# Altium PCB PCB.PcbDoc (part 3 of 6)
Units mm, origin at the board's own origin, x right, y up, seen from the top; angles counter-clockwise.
Board outline 101.6 x 101.61 mm, 4 copper layers (Top Layer, GND, POWER, Bottom Layer), stack 1.371 mm thick; 506 components, 346 nets, 1798 pads, 1471 vias.
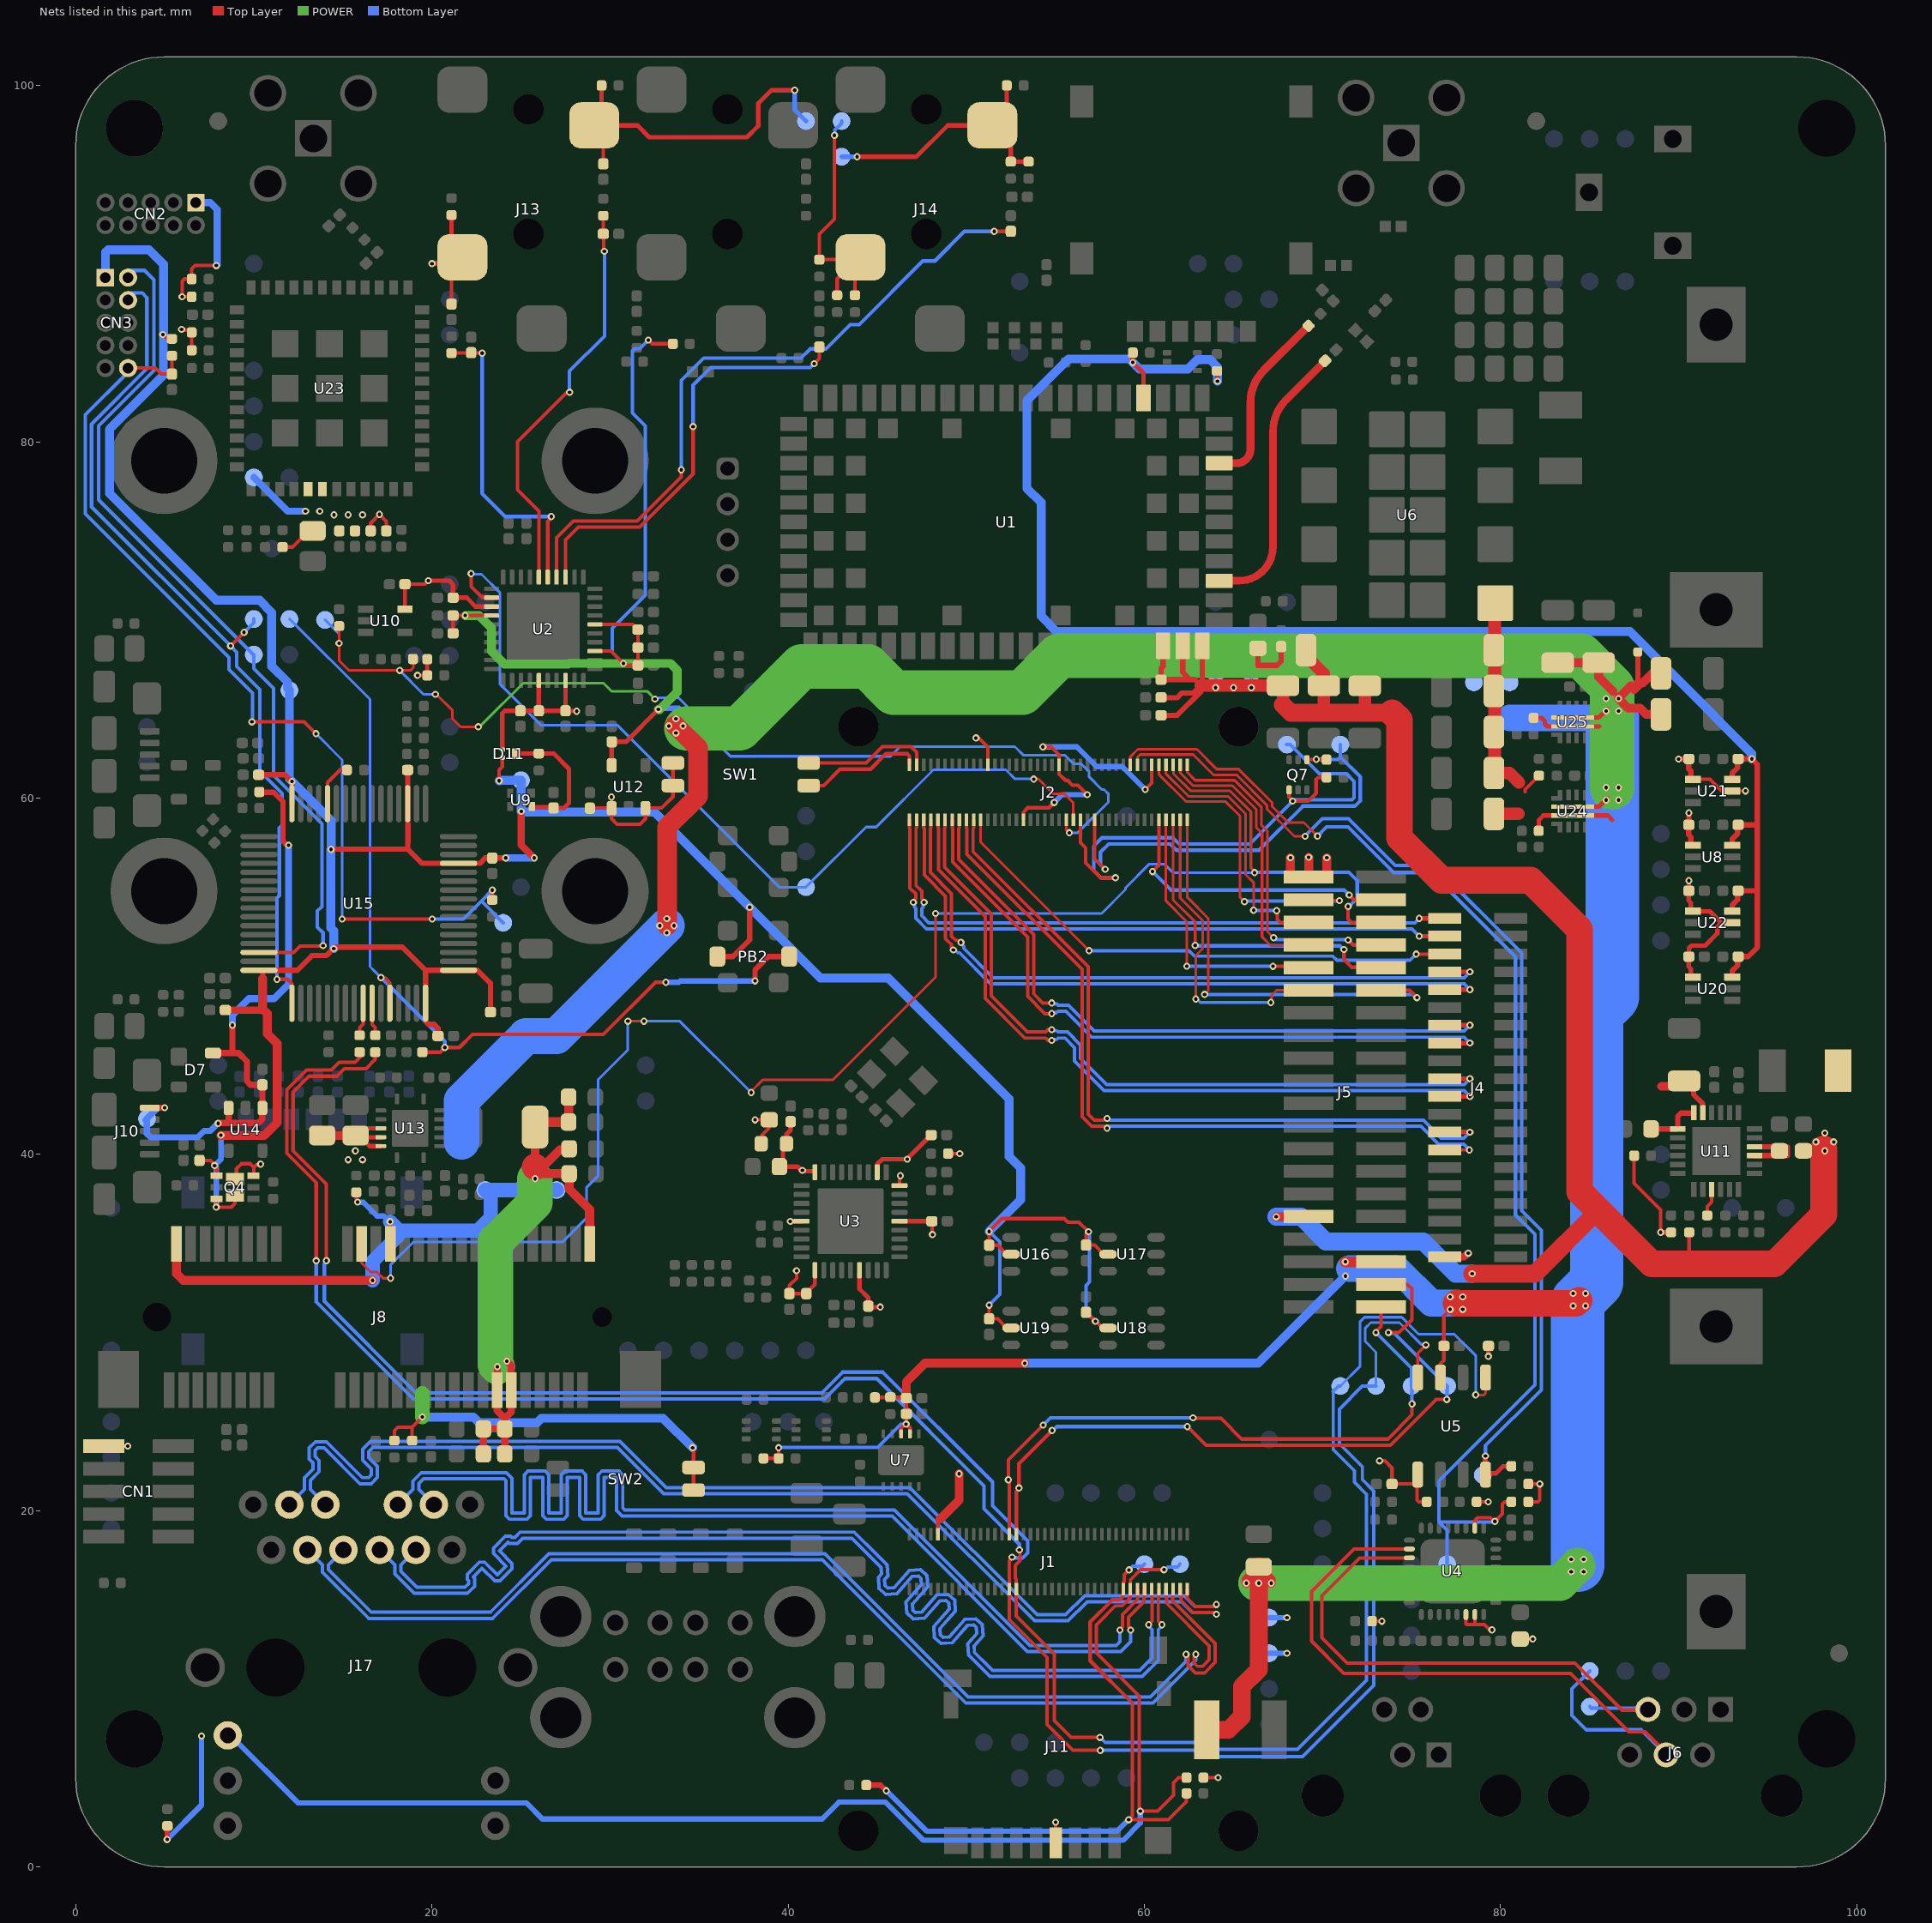
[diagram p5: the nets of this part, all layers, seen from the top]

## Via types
v1: diameter 0.4, hole 0.2, Top Layer to Bottom Layer, tented both sides, 1471 vias

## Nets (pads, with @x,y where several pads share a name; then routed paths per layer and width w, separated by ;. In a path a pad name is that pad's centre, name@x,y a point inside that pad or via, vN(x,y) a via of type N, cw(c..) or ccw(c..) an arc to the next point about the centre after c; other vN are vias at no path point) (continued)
+1V8: 1V8.X C24.2 C25.2 C26.2 C27.2 C28.2 C87.2 R22.2 U2.13 U2.16 U2.34 U12.5 | length 56
  Top Layer w0.2: C25.2@21.185,69.25 C28.2@21.185,70.25 U2.34@23.35,70.25 ; U2.13@29.15,68.25 30.06,68.25 v1(30.75,67.56) 30.86,67.45 C24.2@31.565,67.45 C27.2@31.565,68.45 C26.2@31.565,69.45 31.265,69.75 U2.16@29.15,69.75 ; v1(32.143,85.706) 32.154,85.706 32.36,85.5 R22.2@33.525,85.5
  Top Layer w0.25: U12.5@30.089,61.837 30.089,63.149 C87.2@30.1,63.16 30.893,63.16 v1(32.709,64.976)
  POWER w0.5: v1(21.872,70.246) 22.654,70.246 23.35,69.55 23.35,68.251 24.076,67.525 27.641,67.525 27.677,67.56 v1(30.75,67.56) 33.385,67.56 33.77,67.175 33.77,65.966 32.78,64.976 v1(32.709,64.976)
  Bottom Layer w0.2: v1(30.75,67.56) 30.126,68.184 30.126,69.526 31.985,71.385 31.985,80.89 31.25,81.625 31.25,85.103 31.367,85.22 31.657,85.22 v1(32.143,85.706)
  Bottom Layer w0.3: v1(32.709,64.976) 32.736,64.976 32.8,65.04 33.866,65.04 34.906,64 1V8.X@35,64
+1V8_M: C30.2 C135.2 C137.2 C139.2 R1.2 R2.2 U1.4 U8.6 U20.6 U21.6 U22.6 | length 92.2
  Top Layer w0.25: v1(59.349,84.448) 59.95,83.847 U1.4@59.95,82.45 ; R1.2@64.075,83.975 64.088,83.963 64.088,83.412 v1(64.1,83.4)
  Top Layer w0.3: v1(59.349,84.448) R2.2@59.35,85 ; U20.6@93,49.95 93,50.3 93.3,50.6 C135.2@93.3,51.065 ; U22.6@93,53.65 93,54 93.3,54.3 C139.2@93.3,54.765 ; U8.6@93,57.35 93,57.7 93.3,58 C30.2@93.3,58.465 ; U21.6@93,61.05 93,61.4 93.3,61.7 C137.2@93.3,62.165 ; C135.2@93.335,51.1 93.894,51.1 94.413,51.619 94.413,58.5 ; C139.2@93.335,54.8 94.413,54.8 ; C30.2@93.335,58.5 94.413,58.5 ; C137.2@93.335,62.2 v1(94.1,62.2) 94.413,61.887 94.413,58.5
  Bottom Layer w0.5: v1(64.1,83.4) 64.1,84.189 63.684,84.606 62.962,84.606 62.439,84.082 59.715,84.082 59.147,84.65 55.749,84.65 53.4,82.301 53.4,77.4 54.2,76.6 54.2,70.212 55.062,69.35 87.25,69.35 89.95,66.65 94.1,62.5 v1(94.1,62.2)
+3V3: 3V3_1.X 3V3_2.X C11.2 C12.2 C13.2 C14.2 C15.2 C18.2 C29.2 C32.1 C35.2 C36.2 C37.2 C43.2 C57.2 C59.2 C70.2 C71.2 C76.2 C88.1 C134.2 C136.2 C138.2 CN1.1 CN2.1 D11.2 J1.72 J2.23 J2.34 J2.43 J2.69 J4.20 J5.1 J11.4 L4.1 LoRa_3V3.X Q4.D Q4.D2 R9.2 R10.2 R11.2 R13.2 R14.2 R34.1 R35.1 R43.2 R45.2 R46.2 R47.2 R48.2 R54.2 R71.2 R76.1 R93.2 R94.2 R95.2 R116.2 SW1.3 SW1.4 SW2.3 SW2.4 U2.5 U2.8 U2.33 U3.15 U3.23 U3.27 U4.30 U4.31 U5.5 U8.1 U10.5 U12.1 U12.3 U20.1 U21.1 U21.5 U22.1 U22.5 U23.5 U23.6 | length 155.2
  Top Layer w0.15: U21.5@93,60.4 v1(93.75,60.4)
  Top Layer w0.2: CN1.1@1.578,23.625 v1(2.926,23.625) ; v1(5.941,86.308) 5.979,86.27 6.382,86.27 R10.2@6.514,86.138 R11.2@6.514,85.138 ; R14.2@6.509,88.138 v1(5.974,88.138) 5.974,89.011 6.101,89.138 R9.2@6.509,89.138 6.509,89.694 6.705,89.89 v1(7.891,89.89) ; Q4.D2@8.945,38.622 9.025,38.702 9.025,39.196 9.304,39.475 9.8,39.475 10,39.275 ; Q4.D@9.985,38.805 10,38.82 10,39.275 ; v1(10.38,39.455) 10.342,39.417 10.142,39.417 10,39.275 ; R13.2@11.615,74.09 12.173,74.09 13.083,75 C12.2@13.3,75 ; C15.2@16.56,75 16.56,75.435 v1(17.05,75.925) 17.44,75.535 C11.2@17.44,75 ; R93.2@17.891,23.94 17.891,24.489 18.091,24.689 18.891,24.689 ; U10.5@18.485,70.605 C32.1@18.485,72.005 19.605,72.005 v1(19.8,72.2) ; R94.2@18.891,23.94 18.891,24.689 ; v1(19.191,66.89) R34.1@19.741,66.89 R35.1@19.741,67.79 ; v1(19.462,25.259) v1(19.462,25.259) 18.891,24.689 ; C88.1@28.874,59.433 C88.1@28.87,59.433 28.874,59.438 U12.1@30.089,59.438 ; v1(30.08,60.056) 30.085,60.052 30.085,59.442 U12.1@30.089,59.438 ; SW1.3@33.529,61.973 SW1.4@33.529,60.703 33.529,60.067 32.9,59.438 U12.3@31.989,59.438 31.989,58.838 31.689,58.538 30.389,58.538 30.089,58.838 U12.1@30.089,59.438 ; v1(34.639,23.538) 34.639,23.483 34.685,23.438 SW2.4@34.685,22.425 SW2.3@34.685,21.155 ; v1(38.143,41.938) C76.2@38.939,41.938 38.914,41.913 38.914,41.461 38.53,41.076 38.53,40.65 L4.1@38.48,40.6 ; U3.27@46.25,38.25 46.25,38.75 v1(46.3,38.8) ; C70.2@48.065,36.25 48.082,36.233 48.082,35.518 v1(48.1,35.5) ; 48.407,19.406 48.407,18.996 48.41,18.994 J1.72@48.41,18.685 ; R54.2@48.976,40.047 v1@49.638,40.047 ; v1(50.545,63.377) 50.578,63.344 50.736,63.344 51.21,62.871 J2.23@51.21,61.865 ; J2.34@53.21,58.785 53.21,59.21 53.457,59.457 54.64,59.457 v1(54.935,59.752) ; v1(54.301,62.879) 54.753,62.879 55.21,62.421 J2.43@55.21,61.865 55.21,61.35 55.56,61 55.679,61 55.962,60.717 56.264,60.717 v1(56.791,60.19) ; J11.4@55.018,1.362 v1(55.018,2.518) ; v1(60.044,60.482) 60.41,60.849 J2.69@60.41,61.865 ; R116.2@63.314,5.018 v1(64.139,5.018) ; R43.2@72.78,13.8 v1(73.33,13.8) ; v1(73.2,22.8) 73.5,22.8 73.9,22.4 C59.2@73.9,21.5 75.17,21.5 75.238,21.5 U5.5@75.3,21.562 ; R48.2@75.85,20.5 75.4,20.5 75.3,20.6 U5.5@75.3,21.562 ; U4.30@78.05,14.175 78.05,13.65 78.094,13.606 78.594,13.606 ; U4.31@78.55,14.175 78.55,13.65 78.594,13.606 ; R46.2@78.65,20.5 v1(79.3,20.5) ; C18.2@79.3,29.265 C18.2@79.315,29.25 ; v1(79.515,13.309) 79.509,13.309 79.5,13.3 79.4,13.3 79.094,13.606 78.594,13.606 ; C57.2@81.1,12.8 v1(81.8,12.8) ; R47.2@81.55,20.5 82.1,20.5 82.2,20.6 v1(82.2,21.5) R45.2@81.55,21.5 ; R71.2@87.495,39.93 87.495,38.38 88.986,36.889 v1(88.986,35.625) ; U21.1@90.8,61.05 91.75,61.05 92.4,60.4 U21.5@93,60.4 ; U5.5@75.3,21.562 75.345,21.607 U5.5@75.345,22.025 75.3,21.98 75.3,21.63 U5.5@75.3,21.562
  Top Layer w0.25: v1(19.8,72.2) 20.97,72.2 21.185,71.985 C43.2@21.185,71.25 21.95,71.25 22.45,70.75 U2.33@23.35,70.75 ; D11.2@23.95,62.725 23.95,64.754 24.096,64.9 C35.2@24.967,64.9 C36.2@26,64.9 ; U2.5@26,66.6 C36.2@26,64.9 ; 27.5,65.694 C37.2@27.5,64.9 ; 27.5,65.694 27.5,66.3 U2.8@27.5,66.6 ; v1(28.125,64.875) 28.113,64.888 27.513,64.888 C37.2@27.5,64.9 ; U3.15@44,33.3 44,32.452 44.5,31.952 C71.2@44.5,31.485 44.553,31.432 v1(45.168,31.432) ; U3.23@46.25,36.25 C70.2@48.065,36.25 ; U5.5@75.17,21.5 75.3,21.63 75.345,21.675 U5.5@75.345,22.025 ; v1(79.309,28.666) 79.312,28.669 79.312,29.247 C18.2@79.315,29.25 ; v1(88.986,35.625) R76.1@89.568,35.625 ; C138.2@90.536,54.771 C138.2@90.559,54.794 ; v1(90.565,55.365) C138.2@90.565,54.8 C138.2@90.559,54.794 ; U20.1@90.8,49.95 90.726,49.95 90.676,50 90.676,50.424 90.559,50.541 90.559,51.094 C134.2@90.565,51.1 90.565,51.578 90.711,51.725 91.484,51.725 92.165,52.406 92.165,52.765 92.4,53 ; U22.5@93,53 92.4,53 ; C36.2@26,64.9 C37.2@27.5,64.9 ; C138.2@90.559,54.794 90.559,54.241 90.676,54.124 90.676,53.7 90.726,53.65 U22.1@90.8,53.65 91.75,53.65 92.4,53
  Top Layer w0.3: v1(5.132,1.547) 5.14,1.556 5.14,2.181 5.149,2.19 R95.2@5.149,2.306 ; v1(89.994,62.194) C136.2@90.559,62.194 ; v1(90.565,59.165) C29.2@90.565,58.5 90.559,58.494 90.559,57.941 90.676,57.824 90.676,57.4 90.726,57.35 U8.1@90.8,57.35 ; C136.2@90.565,62.2 C136.2@90.559,62.194 ; U21.1@90.8,61.05 90.726,61.05 90.676,61.1 90.676,61.524 90.559,61.641 C136.2@90.559,62.194
  Top Layer w0.4: J4.20@76.85,34.25 77.958,34.25 78.159,34.451 v1(78.181,34.451)
  Top Layer w0.5: 48.533,19.531 49.6,20.598 v1(49.6,22.075) ; J5.1@68.2,55.547 v1(68.2,56.65) ; J5.1@69.218,55.565 69.225,55.572 v1(69.225,56.675) ; J5.1@70.243,55.547 v1(70.243,56.65)
  POWER w0.8: v1(19.462,25.259) 19.462,26.597
  Bottom Layer w0.3: v1(5.132,1.547) 7.062,3.478 v1(7.062,7.357) ; v1(50.545,63.377) v1@50.572,63.377 ; v1(54.301,62.879) 56.202,62.879 57.316,61.765 58.761,61.765 v1(60.044,60.482) ; v1(54.935,59.752) 55.373,60.19 v1(56.791,60.19) ; 3V3_1.X@67,12 v1(68,12) ; 3V3_2.X@67,14 v1(68,14)
  Bottom Layer w0.4: CN2.1@6.749,93.428 7.553,93.428 7.935,93.046 7.935,89.934 v1(7.891,89.89) ; LoRa_3V3.X@10,78 11.9,76.1 v1(12.9,76.1)
  Bottom Layer w0.5: v1(19.462,25.259) 22.326,25.259 22.642,24.943 25.895,24.943 26.142,25.19 32.987,25.19 v1(34.639,23.538)
  other v1: 49.638,40.047 14.5,75.9 15.3,75.9 16.1,75.9 13.7,76.1
+3V3_CLK_1: C19.2 D11.3 R57.2 U9.4 | length 7.6
  Top Layer w0.25: D11.3@24.65,62.5 R57.2@25.995,62.5 26.837,62.5 27.697,61.64 27.697,59.72 27.417,59.44 26.763,59.44 26.724,59.479 25.651,59.479 U9.4@25.605,59.525
+3V3_DBG: 3V3_DBG.X C63.1 C96.2 C98.2 C99.2 C100.2 C101.2 C102.2 C103.2 C113.1 C114.1 C115.1 CN3.1 D11.1 DBG_3V3.X PB2.6 Q4.K Q4.K2 Q4.S R81.2 U15.1 U15.13 U15.19 U15.32 U15.48 U15.64 U16.5 U17.5 U18.5 U19.5 | length 192
  Top Layer w0.2: v1(4.891,86.023) 5.139,85.775 R81.2@5.4,85.775 ; C96.2@6.955,39.665 7.562,39.665 7.8,39.427 v1(7.8,39.375) ; v1@7.851,39.375 7.905,39.375 Q4.S@7.905,38.805 ; Q4.K@7.905,37.505 7.889,37.489 v1(7.889,37.042) 8.736,37.042 8.941,37.248 8.941,37.684 Q4.K2@8.945,37.688 ; 10.459,48.1 10.501,48.143 ; v1(23.775,60.975) 23.775,61.575 23.95,61.75 D11.1@23.95,62.275 ; v1(51.283,31.541) C63.1@51.283,30.768 51.761,30.768 52.273,30.255 U19.5@52.523,30.255 ; U16.5@52.523,34.392 52.273,34.392 51.761,34.904 C113.1@51.283,34.904 v1(51.283,35.678) 51.283,35.683 52,36.4 55.502,36.4 55.702,36.2 56.324,36.2 v1(56.86,35.663) 56.719,35.521 C115.1@56.719,34.908 57.196,34.908 57.709,34.395 U17.5@57.959,34.395 ; C114.1@56.719,31.138 56.719,31.134 57.225,30.628 v1(57.247,30.628) 57.29,30.628 57.666,30.251 U18.5@57.959,30.251
  Top Layer w0.3: C100.2@10.27,61.311 11.74,61.311 12.119,60.931 v1(12.143,60.931) 12.139,60.927 U15.32@12.139,59.688 ; U15.48@10.289,50.338 U15.48@10.501,50.338 ; 10.501,49.855 U15.48@10.501,50.338 ; v1(14.341,57.121) 14.357,57.138 18.639,57.138 ; C99.2@18.635,61.575 18.639,61.571 U15.19@18.639,59.688 18.639,58.556 18.65,58.545 18.65,57.498 18.639,57.487 18.639,57.138 ; C102.2@20.339,46.648 20.339,47.088 20.131,47.296 19.815,47.296 19.639,47.472 U15.64@19.639,48.488 19.639,50.338 ; C98.2@23.283,47.988 23.283,49.61 22.555,50.338 U15.1@21.489,50.338 19.639,50.338 ; v1(24.139,56.638) C103.2@23.389,56.638 22.989,56.638 22.689,56.338 U15.13@21.489,56.338 19.439,56.338 18.639,57.138 ; PB2.6@36.024,51.1 36.897,51.1 37.843,52.046 v1(37.843,53.875) ; U15.48@10.501,50.338 12.439,50.338 13.261,51.159 14.068,51.159 14.462,51.554 v1(14.489,51.554) 14.516,51.554 14.601,51.639 18.338,51.639 19.639,50.338
  Top Layer w0.4: C101.2@8.4,48.1 10.459,48.1 ; v1(25.016,59.254) 25.016,57.361 v1(25.739,56.638)
  Top Layer w0.5: v1(8.154,41.075) 8.205,41.075 8.214,41.066 10.579,41.066 11.305,41.792 11.305,46.209 10.75,46.764 10.75,47.894 10.501,48.143 10.501,48.245 10.501,49.855
  Bottom Layer w0.2: v1(51.283,31.541) 51.884,32.142 51.884,35.077 v1(51.283,35.678) ; v1(56.86,35.663) 56.899,35.625 56.899,35.525 56.919,35.505 56.919,32.838 56.719,32.638 56.719,31.156 v1(57.247,30.628)
  Bottom Layer w0.3: v1(7.889,37.042) 7.889,39.259 7.8,39.348 v1(7.8,39.375) 8.154,39.73 v1(8.154,41.075)
  Bottom Layer w0.4: v1(24.139,56.638) v1(25.739,56.638)
  Bottom Layer w0.5: CN3.1@1.669,89.618 1.669,90.623 1.816,90.77 4.122,90.77 4.935,89.957 v1@4.935,86.075 ; v1@4.921,86.075 4.921,83.721 1.902,80.702 1.902,77.098 7.9,71.1 10.319,71.1 11,70.419 11,67.403 11.904,66.498 11.904,66.146 DBG_3V3.X@12,66.05 12,61.075 14.341,58.734 v1(14.341,57.121) 14.321,57.101 14.321,52.713 14.489,52.545 v1(14.489,51.554) ; v1(23.775,60.975) 23.8,61 3V3_DBG.X@25,61 25.016,60.984 v1(25.016,59.254) 25.045,59.225 32.493,59.225 v1(37.843,53.875) 41.817,49.9 43.525,49.9 45.607,49.9 52.4,43.107 52.4,39.882 53.05,39.232 53.05,37.445 v1(51.283,35.678)
+3V3_PCIE: 3V3_PCIE.X 3V3_PCIE_1.X 3V3_PCIE_2.X C104.2 C106.2 C125.2 C126.2 C130.2 C131.2 C132.2 C133.2 J8.2 J8.24 J8.39 J8.41 J8.52 L6.2 R64.2 | length 69.4
  Top Layer w0.2: R64.2@15.755,37.865 15.755,37.345 15.775,37.325 v1(15.825,37.325) ; v1(17.647,36.221) 17.647,34.987 J8.24@17.657,34.977
  Top Layer w0.4: C131.2@22.891,23.19 C130.2@22.891,24.59 C133.2@24.091,24.59 ; v1(23.67,28.088) 23.67,26.79 J8.39@23.657,26.777 23.657,25.624 24.089,25.191 ; C132.2@24.091,23.19 C132.2@24.091,23.19 C133.2@24.091,24.59 ; C133.2@24.091,24.59 C133.2@24.091,24.59 ; v1(24.2,28.4) 24.457,28.143 J8.41@24.457,26.777 24.457,25.559 24.089,25.191 ; C133.2@24.091,24.59 24.089,25.191
  Top Layer w0.5: J8.2@5.657,34.977 5.659,34.975 5.659,33.308 6.04,32.928 v1(16.67,32.928) ; 25.789,39.303 L6.2@25.789,41.538 ; 25.862,38.915 C106.2@27.705,38.915 27.705,38.053 28.857,36.901 J8.52@28.857,34.977 ; 26.29,39.136 26.29,39.366 27.166,40.242 27.632,40.242 C104.2@27.705,40.315 ; C125.2@27.675,41.815 C126.2@27.675,43.215
  Top Layer w0.54: L6.2@25.789,41.538 26.066,41.815 C125.2@27.675,41.815
  Top Layer w1.5: 25.789,39.303 25.79,39.302
  POWER w2: v1(23.67,28.088) 23.575,28.183 23.575,35.084 25.79,37.299 v1(25.79,38.636)
  Bottom Layer w0.3: v1(15.825,37.325) 15.844,37.306 16.151,37.306 16.912,36.545 17.297,36.545 17.62,36.221 v1(17.647,36.221)
  Bottom Layer w0.8: v1(16.67,32.928) 16.67,33.99 18.068,35.388 18.068,35.801 v1(17.647,36.221) ; 18.396,35.716 22.566,35.716 23.3,36.45 23.3,37.665 3V3_PCIE_2.X@23,37.965 ; 3V3_PCIE_2.X@23,38 3V3_PCIE_1.X@25,38 3V3_PCIE_1.X@25.135,38 ; v1(25.79,38.636) 25.612,38.458 25.594,38.458 3V3_PCIE_1.X@25.135,38 ; 3V3_PCIE.X@27,38 3V3_PCIE_1.X@25.135,38
+3V3A: C72.2 C73.2 C74.2 C75.2 C77.2 L4.2 U3.5 U3.10 U3.29 U3.36 | length 13.7
  Top Layer w0.2: v1(40.47,33.47) 40.47,33.046 40.068,32.644 C73.2@40.068,32.185 C74.2@41.017,32.185 41.017,32.21 41.5,32.693 U3.10@41.5,33.5
  Top Layer w0.25: v1@40.102,36.25 U3.5@40.75,36.25
  Top Layer w0.26: C72.2@40.139,41.838 40.139,41.373 39.9,41.133 L4.2@39.9,40.6 39.703,40.403 39.703,39.511 C77.2@39.506,39.314 40.521,39.314 40.735,39.1 v1(40.8,39.1) 40.846,39.054 41.49,39.054 41.5,39.044 U3.36@41.5,39 ; U3.29@45,39 45.01,39.01 45.01,39.455 45.286,39.731 v1(46.685,39.731) 46.685,39.759 48.013,41.087 C75.2@48.027,41.087
  other v1: 40.12,36.245
+3V8: 3V8.X 3V8_2.X 3V8_3.X C1.2 C2.2 C3.2 C4.2 C5.2 C6.2 C85.2 C140.2 C141.2 C142.2 C143.2 J5.31 L5.2 R70.1 U1.51 U1.52 U1.53 U11.15 U11.16 | length 124
  Top Layer w0.2: R70.1@90.584,35.625 90.584,33.877 90.6,33.861
  Top Layer w0.3: C4.2@60.935,64.65 60.937,64.648 61.848,64.648 63.175,65.975 63.175,66.31 ; C5.2@60.935,65.65 60.955,65.63 61.83,65.63 62.1,65.9 62.765,65.9 63.175,66.31 ; U1.51@61.05,68.55 61.05,67.389 60.935,67.274 C6.2@60.935,66.65 62.559,66.65 ; U1.52@62.15,68.55 62.15,67.059 62.559,66.65 ; U1.53@63.25,68.55 63.25,66.385 63.175,66.31 ; C2.2@66.375,68.51 C2.2@66.375,68.41 66.375,67.444 67.444,67.444 67.675,67.675 C3.2@67.675,68.51 ; U11.15@94.255,39.93 96.1,39.93 96.1,40.43 U11.16@94.255,40.43 ; 62.559,66.65 62.835,66.65 63.175,66.31
  Top Layer w0.5: v1(67.4,36.5) 69.203,36.5 J5.31@69.218,36.515
  Top Layer w0.7: 63.175,66.31 C143.2@67.775,66.31 67.775,65.232 ; C1.2@69.075,68.31 69.075,67.98 70.075,66.98 C142.2@70.075,66.31 70.075,64.832 70.119,64.788 ; 72.375,64.832 C141.2@72.375,66.31
  Top Layer w1: 67.775,65.232 68.219,64.788 70.119,64.788 73.919,64.788 ; v1(78.4,33.3) 81.927,33.3 85.481,36.854
  Top Layer w1.5: 73.919,64.788 74.319,64.388 74.319,57.762 76.693,55.388 81.671,55.388 84.438,52.62 84.438,37.897 88.475,33.861 90.6,33.861 95.379,33.861 98.143,36.625 v1@98.143,40.301
  Bottom Layer w0.2: 3V8.X@64,67 v1(64,66.2) v1(65,66.2) v1(66,66.2) ; 3V8_3.X@66,67 v1(66,66.2) ; 3V8_2.X@68,67 67.2,66.2 v1(66,66.2)
  Bottom Layer w1: v1(67.4,36.5) 68.8,36.5 70.186,35.114 75.652,35.114 77.467,33.3 v1(78.4,33.3)
  other v1: 98.2,40.2 97.7,40.7 98.7,40.7 98.2,41.2
+5V: 5V.X 5V_1.X 5V_2.X C58.1 C83.2 C94.2 C95.2 C129.2 C148.2 C149.2 C150.2 C151.2 D10.2 F1.2 J5.36 R41.2 R42.2 R56.1 R92.1 R112.2 U5.3 U7.2 U7.3 U13.4 U13.5 U13.6 U24.6 U25.6 | length 262.7
  Top Layer w0.2: R56.1@38.616,22.938 R112.2@39.466,22.938 v1(39.466,23.538) v1@39.466,23.565 ; R42.2@44.869,26.358 46.599,26.358 C95.2@46.639,26.318 C94.2@46.639,25.438 46.639,24.938 v1@46.608,24.906 ; U7.3@46.339,24.313 46.339,24.638 v1@46.608,24.906 ; U7.2@46.839,24.313 46.839,24.674 v1@46.608,24.906 ; U5.3@76.615,27.475 76.615,28.245 76.815,28.445 C58.1@76.815,29.25 ; C58.1@76.811,29.254 C58.1@76.815,29.25 ; v1(77.169,31.3) 76.815,30.946 C58.1@76.815,29.25
  Top Layer w0.25: C83.2@15.71,41.065 15.907,41.065 C83.2@16.007,40.965 ; C83.2@15.958,41.065 16.357,41.465 U13.4@17.13,41.465 ; U13.6@17.13,40.465 16.507,40.465 C83.2@16.007,40.965 ; U13.5@17.13,40.965 C83.2@16.007,40.965 ; U24.6@84.038,59.52 85.514,59.52 v1@85.982,59.988 ; U25.6@84.038,64.52 85.514,64.52 v1@85.982,64.988
  Top Layer w0.3: 87.7,66.45 D10.2@87.7,68.2
  Top Layer w0.5: C129.2@13.83,41.065 C83.2@15.71,41.065 ; C95.2@46.639,26.318 46.639,27.238 47.68,28.279 v1(53.279,28.279) ; v1(65.719,15.938) 65.719,16.156 65.939,16.376 65.939,16.614 66.183,16.859 R92.1@66.422,16.859 ; v1(66.419,15.938) 66.419,16.856 R92.1@66.422,16.859 ; v1(67.119,15.938) 67.119,16.162 66.905,16.376 66.905,16.614 66.661,16.859 R92.1@66.422,16.859 ; C151.2@83.2,67.6 C150.2@85.5,67.6 85.5,66.8 86.3,66 ; v1@86.619,65.681 v1(86.619,65.588) ; 87.315,66.285 v1(86.619,65.588) ; 87.5,66.1 87.7,66.3 87.7,66.45 87.951,66.45 88.501,67 C149.2@89,67 ; C148.2@89,64.7 88.176,64.7 87.819,65.057 87.15,65.057 v1(86.619,65.588)
  Top Layer w0.6: v1(71.282,33.972) v1(71.282,33.972) 73.281,33.974 J5.36@73.282,33.975
  Top Layer w1: F1.2@63.5,7.7 64.731,7.7 65.469,8.438 65.469,10.138 66.422,11.091 R92.1@66.422,16.859
  Top Layer w1.1: 33.2,52.85 33.2,58.366 34.944,60.111 34.944,62.814 33.666,64.092
  Top Layer w1.5: 77.5,31.638 84.238,31.638 84.4,31.8
  POWER w2: v1@66.269,15.938 v1(66.419,15.938) v1(67.119,15.938) 83.342,15.938 84.324,16.92
  POWER w2.5: 34.296,63.912 37.278,63.912 40.754,67.388 44.462,67.388 45.924,65.926 53.15,65.926 55.208,67.984 84.527,67.984 86.269,66.243 86.269,60.588
  Bottom Layer w0.2: v1(39.466,23.538) 39.478,23.55 45.019,23.55 46.321,24.851 46.611,24.851 v1(46.619,24.86)
  Bottom Layer w0.5: v1(53.279,28.279) 66.389,28.279 v1(71.284,33.174)
  Bottom Layer w1.5: 71.503,33.592 74.177,33.592 76.111,31.658 77.56,31.658 ; 5V.X@80.5,64.5 86.257,64.5 86.269,64.488
  Bottom Layer w2: 21.662,40.71 21.662,43.026 25.274,46.638 26.99,46.638 33.189,52.838
  Bottom Layer w3: 84.319,16.938 84.319,31.759 85.391,32.832 85.391,47.961 86.269,48.838 86.269,64.488
  other v1: 83.961,16.572 84.661,16.572 83.961,17.272 84.661,17.272 77.869,31.3 84.069,31.5 84.769,31.5 77.169,32 77.869,32 84.069,32.2 84.769,32.2 15.3,39.7 16.1,39.7 15.7,40.2 33.189,52.438 32.789,52.838 33.589,52.838 33.189,53.238 85.919,59.888 86.619,59.888 85.919,60.588 86.619,60.588 33.7,63.65 33.3,64.05 34.1,64.05 33.7,64.45 85.919,64.888 86.619,64.888 85.919,65.588
+5V_BQ: C64.2 R123.2 U11.23 U25.5 | length 7
  Top Layer w0.25: R123.2@81.85,64.5 82.299,64.5 82.477,64.322 82.477,64.167 82.624,64.02 85.538,64.02
  Top Layer w0.28: C64.2@90.838,43.82 90.838,43.358 91.35,42.846 U11.23@91.35,42.335
  Top Layer w0.5: 89.038,43.82 C64.2@90.338,43.82
+5V_DBG: 5V_DBG.X C97.1 D7.4 J10.1 R125.1 U14.1 U14.3 | length 34.8
  Top Layer w0.3: R125.1@10.31,60.325 11.11,60.325 11.64,59.795 11.64,58.406 11.639,58.405 11.639,57.576 11.846,57.369 11.931,57.369 v1(11.95,57.35)
  Top Layer w0.35: J10.1@4.316,42.62 4.32,42.616 4.989,42.616 v1(4.995,42.622) ; D7.4@7.703,45.688 8.704,45.688 ; v1(7.996,41.743) 8.006,41.753 8.041,41.753 8.048,41.76 8.588,41.76 ; U14.3@8.585,42.605 8.588,42.602 8.588,41.76 ; v1(8.792,47.25) 8.798,47.244 8.798,45.782 8.704,45.688 ; 8.588,41.76 10.26,41.76 10.465,41.965 10.465,42.585 U14.1@10.485,42.605 C97.1@10.485,43.905 9.817,43.905 9.612,44.11 9.612,45.217 9.141,45.688 8.704,45.688
  Bottom Layer w0.35: 5V_DBG.X@3.925,41.925 5V_DBG.X@4,42 ; v1(4.995,42.622) 4.993,42.62 4.62,42.62 5V_DBG.X@4,42 ; v1(7.996,41.743) 7.983,41.743 7.559,41.319 7.208,41.319 6.844,40.955 4.205,40.955 4,41.16 5V_DBG.X@4,42
  Bottom Layer w0.4: v1(8.792,47.25) 8.792,47.81 9.721,48.738 11.126,48.738 11.95,49.562 v1(11.95,57.35)
+5V_MPM: C61.2 C62.2 C92.2 C144.2 C145.2 C146.2 R88.2 R120.2 U6.5 U11.1 U11.24 U24.5 | length 21.9
  Top Layer w0.2: 81.368,60.359 81.368,60.474 R88.2@82.153,61.259 R88.2@82.168,61.259
  Top Layer w0.25: R120.2@82.138,58.159 82.138,58.759 82.399,59.02 U24.5@84.038,59.02 86.014,59.02 86.266,58.768
  Top Layer w0.3: C92.2@88.445,41.43 U11.1@89.945,41.43 89.945,42.141 90.121,42.317 90.85,42.317 U11.24@90.85,42.335
  Top Layer w0.7: C144.2@79.625,59.11 80.997,59.11 ; C145.2@79.625,61.41 C145.2@79.665,61.41 ; U6.5@79.705,70.95 79.665,70.91 C145.2@79.665,61.41 ; 81.019,60.888 80.497,61.41 C145.2@79.665,61.41
\R\S\T\_3: C105.2 CN3.10 DGB_RST.X R81.1 R83.2 | length 54.7
  Top Layer w0.2: CN3.10@2.939,84.138 4.462,84.138 4.8,83.8 C105.2@5.4,83.8 R81.1@5.4,84.825 ; v1(9.888,64.277) 12.826,64.277 v1(13.489,63.615) ; v1(14.96,53.208) 14.962,53.211 15.559,53.211 ; 15.56,53.211 v1(20.012,53.211) ; R83.2@23.389,54.288 v1(23.389,54.838)
  Bottom Layer w0.15: v1(13.489,63.615) 14.96,62.144 v1(14.96,53.208)
  Bottom Layer w0.2: CN3.10@2.939,84.138 2.939,83.839 2.861,83.839 0.541,81.519 0.541,75.959 8.6,67.9 8.6,67.227 9.925,65.902 9.925,64.314 v1(9.888,64.277) ; v1(20.012,53.211) 21.763,53.211 22.776,54.224 ; v1(23.389,54.838) 22.776,54.224 ; DGB_RST.X@24,53 22.776,54.224
A0_1: J2.73 J5.5 | length 15.1
  Top Layer w0.15: J2.73@61.21,61.865 61.21,61.367 62.477,60.1 64.691,60.1 65.678,59.113 65.678,55.717 66.129,55.267 v1(66.129,53.703)
  Top Layer w0.2: v1(67.427,53.677) 67.465,53.639 67.465,53.185 67.625,53.025 J5.5@69.218,53.025
  Bottom Layer w0.2: v1(66.129,53.703) 66.142,53.69 67.414,53.69 v1(67.427,53.677)
A1_1: J2.75 J5.6 J8.20 | length 92
  Top Layer w0.15: J8.20@16.057,34.977 16.057,33.902 16.556,33.403 16.905,33.403 17.258,33.05 v1(17.675,33.05) ; v1(31,47.475) v1@31.901,47.475 ; v1(37.925,43.475) 37.925,43.532 38.568,44.175 42.5,44.175 48.275,49.95 v1(48.275,53.525) ; J2.75@61.61,61.865 61.635,61.84 61.635,61.366 62.602,60.4 64.815,60.4 65.978,59.237 65.978,56.086 66.18,55.885 v1(66.18,55.817)
  Top Layer w0.2: v1(71.438,53.92) 71.438,53.22 71.634,53.025 J5.6@73.282,53.025
  Bottom Layer w0.15: v1(17.675,33.05) 17.675,33.789 18.977,35.091 27.352,35.091 28.675,36.414 28.675,38.136 29.339,38.801 29.339,44.209 31,45.87 v1(31,47.475) ; v1(31.901,47.476) 33.924,47.476 v1(37.925,43.475) ; v1(48.275,53.525) 57.595,53.525 58.939,54.869 58.939,54.964 60.275,56.3 61.124,56.3 61.607,55.817 v1(66.18,55.817)
  Bottom Layer w0.2: v1(66.18,55.817) 66.203,55.84 71.476,55.84 71.947,55.37 71.947,54.37 71.535,53.959 71.477,53.959 v1(71.438,53.92)
A2_1: J2.77 J5.7 | length 15.7
  Top Layer w0.15: J2.77@62.01,61.865 62.01,61.416 62.726,60.7 64.939,60.7 66.278,59.361 66.278,58.349 66.605,58.022 66.605,52.213 67.097,51.72 69.183,51.72 J5.7@69.218,51.755
A3_1: J2.79 J5.8 | length 19.2
  Top Layer w0.15: J2.79@62.41,61.865 62.41,61.44 62.85,61 65.064,61 66.578,59.485 66.578,58.473 66.905,58.146 66.905,52.514 v1(67.253,52.166)
  Top Layer w0.2: v1(71.44,52.029) 71.713,51.755 J5.8@73.282,51.755
  Bottom Layer w0.2: v1(67.253,52.166) 67.307,52.166 67.417,52.056 71.412,52.056 v1(71.44,52.029)
A4_1: J2.74 J5.9 | length 15.6
  Top Layer w0.15: J2.74@61.21,58.785 61.21,54.231 62.383,53.058 v1(62.383,50.562)
  Top Layer w0.2: v1(67.216,50.557) 69.146,50.557 J5.9@69.218,50.485
  Bottom Layer w0.2: v1(62.383,50.562) 62.388,50.557 v1(67.216,50.557)
A5_1: J2.76 J5.10 | length 18.8
  Top Layer w0.15: J2.76@61.61,58.785 61.61,54.285 62.849,53.047 v1(62.849,51.729)
  Top Layer w0.2: v1(71.2,51.5) 71.2,50.95 71.3,50.85 71.65,50.5 73.267,50.5 J5.10@73.282,50.485
  Bottom Layer w0.2: v1(62.849,51.729) 62.871,51.706 70.982,51.706 71.188,51.5 v1(71.2,51.5)
A6_1: J2.78 J5.11 | length 17.7
  Top Layer w0.15: J2.78@62.01,58.785 62.01,54.393 63.274,53.129 63.274,51.553 62.883,51.162 v1(62.883,48.718) ; v1(67.1,48.531) 67.148,48.578 67.148,48.953 67.41,49.215 J5.11@69.218,49.215
  Bottom Layer w0.15: v1(62.883,48.718) 62.951,48.718 63.138,48.531 v1(67.1,48.531)
A7_1: J2.80 J5.12 | length 24.6
  Top Layer w0.15: J2.80@62.41,58.785 62.41,54.42 63.587,53.243 63.587,49.194 63.381,48.988 v1(63.381,48.981)
  Top Layer w0.2: J5.12@73.282,49.215 74.885,49.215 v1(75.3,48.8)
  Bottom Layer w0.2: v1(63.381,48.981) 75.065,48.981 75.246,48.8 v1(75.3,48.8)
A_13: A.X J6.4 U4.18 | length 41
  Top Layer w0.2: U4.18@74.875,17.85 71.77,17.85 69.384,15.464 69.384,12.687 71.196,10.874 83.926,10.874 87.2,7.6 88.1,7.6 89.29,6.41 J6.4@89.29,6.3
  Bottom Layer w0.2: A.X@85,11 84,10 84,8.509 84.809,7.7 87.89,7.7 J6.4@89.29,6.3
AIN2A_4: C39.2 R32.1 U2.25 | length 17.5
  Top Layer w0.2: R32.1@21.1,84.975 21.112,84.987 22.808,84.987 v1(22.819,84.976) ; U2.25@26.5,72.4 26.5,75.519 26.7,75.719 v1(26.7,75.8)
  Bottom Layer w0.2: v1@22.816,84.928 22.816,77.102 24.118,75.8 v1(26.7,75.8)
AIN2B_4: C40.1 R33.1 U2.26 | length 22.9
  Top Layer w0.19: U2.26@26,72.4 26,76.1 24.8,77.3 24.8,80 27.538,82.738 27.689,82.738 v1(27.727,82.777) ; R33.1@29.622,92.687 29.619,92.684 29.619,91.672 C40.1@29.616,91.67 29.649,91.637 29.649,90.724 v1(29.682,90.692) v1@29.684,90.694
  Bottom Layer w0.19: v1(27.727,82.777) 27.727,83.977 29.682,85.932 v1(29.682,90.692)
AIN3A_4: C42.1 U2.23 | length 24.1
  Top Layer w0.2: U2.23@27.5,72.4 27.5,74.489 28.216,75.205 31.672,75.205 34.66,78.193 v1(34.66,80.85) ; v1(41.461,84.384) 41.75,84.673 C42.1@41.75,85.315
  Bottom Layer w0.2: v1(34.66,80.85) 34.66,83.179 35.656,84.175 41.244,84.175 41.453,84.384 v1(41.461,84.384)
AIN3B_4: C47.1 U2.24 | length 38
  Top Layer w0.2: U2.24@27,72.4 27,74.612 27.943,75.555 31.527,75.555 34,78.028 v1(34,78.425) ; v1(51.566,91.809) 51.569,91.812 52.497,91.812 C47.1@52.5,91.815
  Bottom Layer w0.2: v1(34,78.425) 34,83.438 35.262,84.7 40.722,84.7 41.233,85.212 42.112,85.212 43.482,86.582 43.982,86.582 47.55,90.15 48.238,90.15 49.897,91.809 v1(51.566,91.809)
ANALOG.VREF_1_N: J2.72 J5.4 | length 16.5
  Top Layer w0.2: v1(60.451,55.875) 60.81,56.234 J2.72@60.81,58.785 ; v1(71.497,54.557) 71.758,54.295 J5.4@73.282,54.295
  Bottom Layer w0.2: v1(60.451,55.875) 61.488,54.838 71.216,54.838 v1(71.497,54.557)
ANALOG.VREF_1_P: J2.71 J5.3 | length 18.1
  Top Layer w0.15: J2.71@60.81,61.865 60.81,61.343 62.353,59.8 64.567,59.8 65.358,59.008 65.358,54.448 v1(65.619,54.187)
  Top Layer w0.2: J5.3@69.218,54.295 69.271,54.242 v1(70.946,54.242)
  Bottom Layer w0.2: v1(65.619,54.187) 65.646,54.215 70.919,54.215 v1(70.946,54.242)
ANT_5: C8.1 U1.56 | length 15.6
  Top Layer w0.425: U1.56@64.2,72.2 65.314,72.2 ccw(c65.314,74.101) 67.215,74.101 67.215,80.563 cw(c69.755,80.563) 67.959,82.359 C8.1@70.142,84.542
ANT_DET_5: R6.1 U1.62 | length 10.4
  Top Layer w0.447: U1.62@64.2,78.8 65.183,78.8 ccw(c65.183,79.566) 65.95,79.566 65.95,82.198 cw(c68.49,82.198) 66.694,83.994 R6.1@69.214,86.514
AUDIO_MCLK_EN_1: J2.46 MCLK_EN.X R61.1 R62.2 | length 58.9
  Top Layer w0.15: R62.2@14.785,69.655 v1(14.785,68.689) 14.785,67.723 15.344,67.164 18.798,67.164 18.957,67.324 18.957,67.727 R61.1@19.035,67.805 ; v1(20.191,65.827) 20.248,65.827 21.152,64.923 21.152,64.449 21.601,64 v1(22.6,64) ; J2.46@55.61,58.785 55.61,58.23 v1(55.785,58.055)
  POWER w0.15: v1(22.6,64) 22.668,64 22.868,64.2 22.874,64.2 25.124,66.45 29.63,66.45 30.08,66 32.079,66 v1(32.517,65.562)
  Bottom Layer w0.15: MCLK_EN.X@14,70 14.785,69.215 v1(14.785,68.689) ; v1(18.191,67.165) 19.528,65.827 v1(20.191,65.827) ; v1(32.517,65.562) 32.565,65.609 32.707,65.609 32.73,65.632 33.842,65.632 34.708,64.766 35.334,64.766 35.749,64.351 35.749,63.351 36.752,62.348 45.748,62.348 46.291,62.89 52.728,62.89 53.217,62.401 55.547,62.401 56.031,61.917 56.459,61.917 56.898,61.479 56.898,61.19 57.609,60.479 57.732,60.479 57.981,60.23 57.981,59.78 56.256,58.055 v1(55.785,58.055)
AUDIO_RST_1: AUDIO_RST.X J2.48 U2.32 | length 50.7
  Top Layer w0.15: v1(53.791,61.065) 53.816,61.09 54.028,61.09 54.882,60.236 55.509,60.236 56.01,59.735 J2.48@56.01,58.785
  Top Layer w0.2: v1(22.2,72.6) 22.2,71.875 22.8,71.275 23.325,71.275 U2.32@23.35,71.25
  Bottom Layer w0.15: v1(22.2,72.6) 22.238,72.562 22.785,72.562 23.808,71.539 23.808,66.415 26.124,64.1 30.395,64.1 39.495,55 AUDIO_RST.X@41,55 44.372,58.372 44.939,58.372 48.157,61.59 52.222,61.59 52.739,61.073 53.782,61.073 v1(53.791,61.065)
B_13: B.X J6.5 U4.19 | length 31.5
  Top Layer w0.2: U4.19@74.875,17.35 72.088,17.35 69.971,15.232 69.971,12.867 71.386,11.452 84.165,11.452 86.809,8.809 88.239,8.809 J6.5@88.27,8.84
  Bottom Layer w0.2: B.X@85,9 85.08,8.92 88.19,8.92 J6.5@88.27,8.84
BOOT1_3: R79.2 U15.28 | length 2.6
  Top Layer w0.2: U15.28@14.139,59.688 14.139,60.879 14.835,61.575 R79.2@15.235,61.575
BOOT_1: J2.1 SW1.1 | length 7
  Top Layer w0.2: SW1.1@41.149,60.703 41.996,60.703 42.916,61.623 44.518,61.623 44.521,61.626 44.626,61.626 45.491,62.49 46.685,62.49 46.81,62.365 J2.1@46.81,61.865
BT_SEL_1: J2.3 SW1.2 | length 7.3
  Top Layer w0.2: SW1.2@41.149,61.973 44.373,61.973 45.291,62.89 46.891,62.89 47.21,62.571 J2.3@47.21,61.865
CAMERA.CK_1_N: J2.20 J4.13 | length 42.9
  Top Layer w0.19: J2.20@50.41,58.785 50.41,58.332 50.38,58.302 50.38,56.995 56.842,50.533 56.842,42.251 57.176,41.917 57.74,41.917 57.845,42.022 v1(57.902,42.022)
  Top Layer w0.26: J4.13@76.85,41.25 v1(78.275,41.25)
  Bottom Layer w0.19: v1(57.902,42.022) 57.959,42.022 58.064,41.917 75.66,41.917 76.657,40.919 77.931,40.919 78.261,41.25 v1(78.275,41.25)
CAMERA.CK_1_P: J2.18 J4.14 | length 43.4
  Top Layer w0.19: J2.18@50.01,58.785 50.01,58.332 50.04,58.302 50.04,56.854 56.502,50.392 56.502,42.11 57.035,41.577 57.74,41.577 57.845,41.472 v1(57.902,41.472) ; J4.14@76.85,40.25 J4.14@76.85,40.25 v1(78.247,40.249)
  Bottom Layer w0.19: v1(57.902,41.472) 57.959,41.472 58.064,41.577 75.519,41.577 76.516,40.579 77.931,40.579 78.247,40.263 v1(78.247,40.249)
CAMERA.D0_1_N: J2.16 J4.7 | length 38.4
  Top Layer w0.19: J2.16@49.61,58.785 49.61,58.332 49.58,58.302 49.58,56.556 53.79,52.346 53.79,49.9 53.79,49.01 54.3,48.5 v1(54.8,48.5)
  Top Layer w0.26: J4.7@76.85,47.25 v1(78.275,47.25)
  Bottom Layer w0.19: v1(54.8,48.5) 54.859,48.441 55.079,48.441 55.149,48.37 55.73,48.37 57.18,46.92 57.6,46.92 77.945,46.92 v1(78.275,47.25)
CAMERA.D0_1_P: J2.14 J4.8 | length 39.1
  Top Layer w0.19: J2.14@49.21,58.785 49.21,58.332 49.24,58.302 49.24,56.415 53.45,52.205 53.45,49.9 53.45,48.869 54.419,47.9 v1(54.8,47.9)
  Top Layer w0.26: J4.8@76.85,46.25 v1(78.275,46.25)
  Bottom Layer w0.19: v1(54.8,47.9) 54.859,47.959 55.05,47.959 ; 55.05,47.93 55.149,48.03 55.589,48.03 57.039,46.58 57.6,46.58 77.945,46.58 v1(78.275,46.25)
CAMERA.D1_1_N: J2.12 J4.10 | length 42
  Top Layer w0.19: J2.12@48.81,58.785 48.81,58.332 48.78,58.302 48.78,56.114 51.303,53.591 51.403,53.491 51.403,48.897 53.43,46.87 54.451,46.87 54.581,47 v1(54.8,47)
  Top Layer w0.26: J4.10@76.85,44.25 v1(78.275,44.25)
  Bottom Layer w0.19: v1(54.8,47) 54.859,46.941 55.079,46.941 55.149,46.87 55.684,46.87 56.42,46.133 56.42,45.38 57.88,43.92 77.804,43.92 77.945,43.92 v1(78.275,44.25)
CAMERA.D1_1_P: J2.10 J4.11 | length 42.6
  Top Layer w0.19: J2.10@48.41,58.785 48.41,58.332 48.44,58.302 48.44,55.973 51.063,53.35 51.063,48.756 53.289,46.53 54.451,46.53 54.581,46.4 v1(54.8,46.4)
  Top Layer w0.26: J4.11@76.85,43.25 v1(78.275,43.25)
  Bottom Layer w0.19: v1(54.8,46.4) 54.859,46.459 55.079,46.459 55.149,46.53 55.543,46.53 56.08,45.993 56.08,45.239 57.739,43.58 77.945,43.58 v1(78.275,43.25)
CAMERA.D2_1_N: J2.8 J4.4 | length 38.8
  Top Layer w0.19: J2.8@48.01,58.785 48.01,58.332 47.98,58.302 47.98,55.825 49.174,54.631 49.174,52.242 49.396,52.02 49.523,52.02 49.643,51.9 v1(49.7,51.9)
  Top Layer w0.26: J4.4@76.85,50.25 v1(78.275,50.25)
  Bottom Layer w0.19: v1(49.7,51.9) 49.7,51.816 49.855,51.661 49.855,51.561 51.496,49.92 52.4,49.92 77.945,49.92 v1(78.275,50.25)
CAMERA.D2_1_P: J2.6 J4.5 | length 39.3
  Top Layer w0.19: J2.6@47.61,58.785 47.61,58.332 47.64,58.302 47.64,55.684 48.834,54.49 48.834,52.101 49.156,51.78 49.156,51.653 49.276,51.533 v1(49.276,51.476)
  Top Layer w0.26: J4.5@76.85,49.25 v1(78.275,49.25)
  Bottom Layer w0.19: v1(49.276,51.476) 49.36,51.476 49.515,51.321 49.615,51.321 51.355,49.58 52.4,49.58 77.945,49.58 v1(78.275,49.25)
CAMERA.D3_1_N: J2.4 J4.1 | length 35.3
  Top Layer w0.19: J2.4@47.21,58.785 47.205,58.78 47.205,58.327 47.18,58.302 47.18,55.095 47.5,54.775 47.5,54.364 47.63,54.234 v1(47.63,54.15)
  Top Layer w0.26: v1(75.425,53.25) J4.1@76.85,53.25
  Bottom Layer w0.19: v1(47.63,54.15) 47.571,54.091 47.571,53.871 47.5,53.801 47.5,53.4 47.897,53.003 75.178,53.003 v1(75.425,53.25)
CAMERA.D3_1_P: J2.2 J4.2 | length 35.9
  Top Layer w0.19: J2.2@46.81,58.785 46.815,58.78 46.815,58.327 46.84,58.302 46.84,54.954 47.16,54.634 47.16,54.364 47.03,54.234 v1(47.03,54.15)
  Top Layer w0.26: v1(75.425,52.25) J4.2@76.85,52.25
  Bottom Layer w0.19: v1(47.03,54.15) 47.089,54.091 47.089,53.871 47.16,53.801 47.16,53.259 47.756,52.663 75.012,52.663 v1(75.425,52.25)
CAMERA.HS_1: J2.22 J4.3 | length 30.2
  Top Layer w0.15: J2.22@50.81,58.785 50.81,57.518 v1(56.891,51.437)
  Top Layer w0.19: v1(75.261,51.242) 76.793,51.242 76.817,51.217 J4.3@76.85,51.25
  Bottom Layer w0.19: v1(56.891,51.437) 62.51,51.437 62.819,51.129 70.571,51.129 70.81,50.89 74.909,50.89 v1(75.261,51.242)
CAN0.RX_1: CAN0_RX.X J1.52 J5.40 | length 35.9
  Top Layer w0.2: J1.52@52.41,18.685 52.41,21.636 52.36,21.686 52.36,22.848 v1(54.314,24.802) ; v1(62.729,25.211) 62.751,25.189 64.299,25.189 65.467,24.021 73.665,24.021 75.026,25.382 v1@75.026,26.054 ; v1(73,30) 73,30.054 73.282,30.336 J5.40@73.282,31.435
  Bottom Layer w0.2: v1(54.314,24.802) 54.723,25.211 v1(62.729,25.211) ; v1(73,30) 75,28 CAN0_RX.X@75,27 ; CAN0_RX.X@75.013,26.987 75.013,26.013 v1(75.026,25.999)
  other v1: 52.36,21.74
CAN0.TX_1: CAN0_TX.X J1.50 J5.38 | length 40.9
  Top Layer w0.2: J1.50@52.81,18.685 52.81,21.072 52.957,21.219 52.957,22.649 v1(54.815,24.507) ; v1(62.408,24.725) 63.463,23.671 73.81,23.671 75.376,25.237 76.382,26.242 v1(76.976,26.242) ; J5.38@73.282,32.705 74.757,32.705 75.011,32.451 75.011,30.714 74.3,30.002 73.702,30.002 v1(73.7,30)
  Bottom Layer w0.2: v1(54.815,24.507) 54.869,24.507 55.088,24.725 v1(62.408,24.725) ; v1(73.7,30) 73.738,29.962 74.038,29.962 CAN0_TX.X@77,27 76.988,26.988 76.988,26.254 v1(76.976,26.242)
  other v1: 52.957,21.273
CAN1.RX_1: CAN1_RX.X J1.51 R40.2 U5.4 | length 126.4
  Top Layer w0.15: U5.4@75.345,27.475 75.345,28.845 v1(75.8,29.3)
  Top Layer w0.19: v1(52.575,17.391) 52.575,17.334 52.41,17.17 J1.51@52.41,15.605 52.41,13.89 54.53,11.77 54.53,8.006 55.985,6.551 v1(57.526,6.551)
  Top Layer w0.2: v1(14.073,34.04) 14.073,38.336 12.2,40.209 12.2,43.481 13.111,44.392 14.666,44.392 15.089,44.814 16.302,44.814 16.819,45.331 R40.2@16.819,45.738
  Bottom Layer w0.15: CAN1_RX.X@73,27 73,28.9 72.4,29.5 72.4,30.258 72.705,30.562 74.32,30.562 75.541,29.342 75.758,29.342 v1(75.8,29.3)
  Bottom Layer w0.19: v1(57.526,6.551) 62.849,6.551 63.2,6.2 68.881,6.2 72.885,10.204 72.885,21.094 72.237,21.742 72.237,22.462 70.94,23.759 70.94,25.707 72.233,27 CAN1_RX.X@73,27
  Bottom Layer w0.2: v1(14.073,34.04) 14.073,33.985 13.959,33.872 13.959,31.766 19.106,26.619 41.9,26.619 43.056,27.776 45.314,27.776 51.473,21.616 51.473,20.278 53.454,18.297 53.454,17.636 53.169,17.351 52.796,17.351 52.793,17.353 52.613,17.353 v1(52.575,17.391)
CAN1.TX_1: CAN1_TX.X J1.49 R21.2 U5.1 | length 128.1
  Top Layer w0.15: v1(78.6,26.5) 79.067,26.5 79.155,26.588 U5.1@79.155,27.475
  Top Layer w0.19: v1(52.982,17.801) 53.02,17.763 53.02,17.207 52.755,16.942 52.755,16.216 52.81,16.161 J1.49@52.81,15.605 52.81,14.09 54.94,11.96 54.94,8.221 55.885,7.275 v1(57.504,7.275)
  Top Layer w0.2: v1(13.506,34.031) 13.506,38.408 11.85,40.064 11.85,43.626 12.966,44.742 14.361,44.742 14.796,45.177 15.676,45.177 15.939,45.44 R21.2@15.939,45.738
  Bottom Layer w0.15: CAN1_TX.X@71,27 72.1,28.1 72.1,30.6 72.362,30.862 74.444,30.862 75.394,29.912 77.398,29.912 78.6,28.71 v1(78.6,26.5)
  Bottom Layer w0.19: v1(57.504,7.275) 57.794,6.986 63.114,6.986 63.5,6.6 68.6,6.6 72.473,10.473 72.473,20.92 71.786,21.607 71.786,22.243 70.6,23.428 70.6,26.7
  Bottom Layer w0.2: v1(13.506,34.031) 13.506,31.724 18.961,26.269 42.045,26.269 43.196,27.421 44.965,27.421 50.999,21.387 50.999,20.106 52.982,18.123 v1(52.982,17.801) ; 70.6,26.7 70.9,27 CAN1_TX.X@71,27
CAN2_RX_3: R21.1 U15.57 | length 1.9
  Top Layer w0.2: R21.1@15.939,46.688 15.939,47.113 16.139,47.313 U15.57@16.139,48.488
CAN2_TX_3: R40.1 U15.58 | length 1.9
  Top Layer w0.2: U15.58@16.639,48.488 16.639,47.293 16.819,47.113 R40.1@16.819,46.688
CE_bq_12: R74.2 U11.9 | length 1.6
  Top Layer w0.2: R74.2@91.6,36.575 91.6,37.082 91.85,37.332 U11.9@91.85,38.025
CELL_PON_1: J2.54 PWR_ON.X Q7.4 R17.2 | length 26.3
  Top Layer w0.2: J2.54@57.21,58.785 57.21,56.59 v1(57.8,56) ; Q7.4@69.125,62.16 R17.2@70.225,62.16
  Bottom Layer w0.2: v1(57.8,56) 57.532,56.268 57.532,56.957 57.998,57.423 61.45,57.423 61.799,57.074 66.419,57.074 68.895,59.55 71.825,59.55 72.12,59.845 72.12,61.19 71,62.31 ; v1(69.652,62.176) 69.657,62.17 70.86,62.17 71,62.31 ; PWR_ON.X@71,63 71,62.31
CELL_RST_1: J2.50 Q7.1 R3.2 RST.X | length 32.5
  Top Layer w0.2: J2.50@56.41,58.785 56.41,57.49 56.7,57.2 56.7,56.364 57.537,55.528 v1(58.376,55.528) ; Q7.1@68.125,60.46 68.125,60.054 68.322,59.858 v1(68.322,59.827) 69.202,59.827 69.637,60.262 69.637,61.043 69.754,61.16 R3.2@70.225,61.16
  Bottom Layer w0.2: v1(58.376,55.528) 57.558,55.528 57.154,55.931 57.154,57.307 57.621,57.773 61.595,57.773 61.944,57.424 65.919,57.424 v1(68.322,59.827) 68.395,59.9 71.653,59.9 71.77,60.017 71.77,60.945 71.347,61.368 69.819,61.368 68.187,63 RST.X@68,63
CS_AIN2A_4: C38.2 CS_AIN2B.X J13.3 R25.2 | length 7.8
  Top Layer w0.2: C38.2@21.1,87.735 21.103,87.738 21.103,89.75 21.352,90 J13.3@21.712,90.36
  Top Layer w0.25: v1(20,90) J13.3@21.352,90 ; R25.2@21.1,92.725 21.1,90.972 J13.3@21.712,90.36
  Bottom Layer w0.25: v1(20,90) CS_AIN2B.X@21,90
CS_AIN2B_4: C41.2 CS_AIN2A.X J13.2 R24.2 | length 18.8
  Top Layer w0.2: C41.2@29.622,95.597 J13.2@29.622,96.672
  Top Layer w0.25: R24.2@29.525,100 29.525,98.173 J13.2@29.112,97.76 31.54,97.76 32.2,97.1 37.683,97.1 38.317,97.734 38.317,98.989 39.054,99.727 v1(40.366,99.727)
  Bottom Layer w0.25: v1(40.366,99.727) 40.366,98.634 CS_AIN2A.X@41,98
CS_AIN3A_4: CS_AIN3B.X J14.3 R29.2 R36.2 R37.2 | length 14.2
  Top Layer w0.2: v1(42.6,97.2) 42.6,92.5 41.75,91.65 R29.2@41.75,90.225 43.885,90.225 J14.3@43.907,90.203 ; R37.2@42.75,88.225 42.75,89.146 43.381,89.776 43.75,89.776 R36.2@43.75,88.225
  Bottom Layer w0.2: v1@42.6,97.254 v1(42.6,97.2) 42.625,97.225 42.625,97.5 43,97.875 CS_AIN3B.X@43,98
CS_AIN3B_4: CS_AIN3A.X J14.2 R28.2 R38.2 R39.2 | length 15.2
  Top Layer w0.25: v1(43.869,95.996) 47.196,95.996 48.96,97.76 J14.2@51.464,97.76 ; R28.2@52.275,100 52.275,98.571 J14.2@51.464,97.76 ; R39.2@53.5,95.725 R38.2@52.5,95.725 52.5,96.54 51.464,97.576 J14.2@51.464,97.76
  Bottom Layer w0.25: CS_AIN3A.X@43,96 43.002,95.998 43.867,95.998 v1(43.869,95.996)
DBG_BOOT0_3: DBG_BOOT.X PB2.5 R82.2 U15.60 | length 52.6
  Top Layer w0.2: v1(17.139,49.927) 17.178,49.889 17.388,49.889 17.639,49.638 U15.60@17.639,48.488 ; R82.2@19.459,45.738 19.463,45.733 20.458,45.733 v1(20.725,46) 21.543,46 22.281,46.738 29.626,46.738 32.548,49.66 v1(33.135,49.66)
  Top Layer w0.3: v1(38.139,49.738) 38.139,50.35 38.889,51.1 PB2.5@40.054,51.1
  Bottom Layer w0.15: DBG_BOOT.X@12,70.05 12.018,70.05 16.525,65.543 16.525,50.541 16.772,50.294 v1(17.139,49.927)
  Bottom Layer w0.2: v1(17.139,49.927) 20.725,46.341 v1(20.725,46)
  Bottom Layer w0.3: v1(33.135,49.66) 33.857,49.66 33.935,49.738 v1(38.139,49.738)
DBG_SWCLK_3: CN3.4 DBG_SWCLK.X U15.49 | length 49.3
  Top Layer w0.2: v1(8.692,68.539) v1(9.453,69.3) ; v1(11.3,49.831) 11.892,49.831 12.139,49.583 U15.49@12.139,48.488
  Bottom Layer w0.2: CN3.4@2.939,88.348 3.733,88.348 3.991,88.09 3.991,84.091 0.891,80.991 0.891,76.341 v1(8.692,68.539) 9.04,68.192 9.04,67.395 10.338,66.097 10.338,61.509 11.593,60.255 11.593,58.47 11.43,58.308 11.43,54.523 11.3,54.393 v1(11.3,49.831) ; v1(9.453,69.3) 10,69.847 DBG_SWCLK.X@10,70.05
DBG_SWDIO_3: CN3.2 DBG_SWDIO.X U15.46 | length 49.5
  Top Layer w0.2: U15.46@10.289,51.338 12.238,51.338 12.6,51.7 13.868,51.7 v1(13.889,51.721)
  Bottom Layer w0.2: CN3.2@2.939,89.618 3.863,89.618 4.391,89.09 4.391,83.991 1.291,80.891 1.291,76.741 9.982,68.05 DBG_SWDIO.X@10,68.05 10,67.261 11.1,66.161 11.1,61.267 13.821,58.547 13.821,53.917 13.571,53.667 13.571,52.756 13.889,52.437 v1(13.889,51.721)
E\N\_\C\A\N\_1: EN_CAN.X J2.65 R49.1 U5.8 | length 61.4
  Top Layer w0.15: J2.65@59.61,61.865 59.61,62.29 59.76,62.44 62.74,62.44 63.88,61.3 65.188,61.3 66.878,59.61 66.878,59.397 68.42,57.855 v1(69.022,57.855)
  Top Layer w0.25: v1(79.145,23.074) 79.15,23.069 79.15,22.03 79.22,22.1 79.73,22.1 80.13,22.5 R49.1@80.6,22.5
  Bottom Layer w0.2: v1(69.022,57.855) 69.022,57.881 69.991,58.85 71.455,58.85 74.079,56.226 76.257,56.226 81.182,51.3 81.182,36.841 82.282,35.741 82.282,26.786 79.145,23.649 v1(79.145,23.074) 79.106,23.036 79.106,22.106 EN_CAN.X@79,22
EN_485_1: EN_485.X J2.63 R47.1 U4.10 | length 71.1
  Top Layer w0.15: J2.63@59.21,61.865 59.21,62.314 59.636,62.74 62.94,62.74 64.054,61.626 65.286,61.626 67.178,59.734 67.178,59.521 68.071,58.628 68.956,58.628 v1(69.716,57.868)
  Top Layer w0.2: U4.10@78.55,19.025 78.55,19.45 78.7,19.6 79.421,19.6 79.621,19.4 v1(79.675,19.4) 80.1,19.825 80.1,20.37 80.23,20.5 R47.1@80.6,20.5
  Bottom Layer w0.2: v1(69.716,57.868) 70.23,58.382 71.428,58.382 73.984,55.826 76.092,55.826 80.832,51.085 80.832,36.608 81.932,35.509 81.932,27.069 76.53,21.667 76.53,19.373 ; EN_485.X@77,17 77,18.903 76.53,19.373 ; v1(79.675,19.4) 79.648,19.373 76.53,19.373
ETH.A_1_N: J1.3 J17.10 | length 65.3
  Top Layer w0.19: J1.3@62.01,15.605 62.015,15.6 62.015,15.147 62.055,15.107 62.055,14.952 62.714,14.293 63.877,14.293 63.982,14.188 v1(64.039,14.188)
  Bottom Layer w0.19: J17.10@14.02,20.34 13.175,21.185 13.175,21.7 13.669,22.194 13.669,22.821 13.447,23.042 13.447,23.388 13.595,23.536 13.941,23.536 15.958,21.518 16.585,21.518 16.933,21.865 16.933,22.493 16.455,22.97 16.455,23.316 16.699,23.56 17.173,23.56 30.409,23.56 33.009,20.96 46.691,20.96 53.832,13.819 55.719,13.819 56.796,14.896 62.1,14.896 62.703,14.293 63.877,14.293 63.982,14.188 v1(64.039,14.188)
ETH.A_1_P: J1.1 J17.11 | length 65.3
  Top Layer w0.19: J1.1@62.41,15.605 62.405,15.6 62.405,15.26 62.395,15.25 62.395,15.093 62.855,14.633 63.877,14.633 63.982,14.738 v1(64.039,14.738)
  Bottom Layer w0.19: J17.11@11.99,20.34 12.835,21.185 12.835,21.841 12.935,21.94 13.329,22.334 13.329,22.68 13.107,22.901 13.107,23.528 13.454,23.876 14.081,23.876 16.099,21.858 16.444,21.858 16.593,22.006 16.593,22.352 16.115,22.829 16.115,23.457 16.558,23.9 16.834,23.9 30.55,23.9 33.15,21.3 46.832,21.3 53.973,14.159 55.578,14.159 56.655,15.236 62.241,15.236 62.844,14.633 63.877,14.633 63.982,14.738 v1(64.039,14.738)
ETH.B_1_N: J1.7 J17.5 | length 64.3
  Top Layer w0.19: J1.7@61.21,15.605 61.21,15.152 61.24,15.122 61.24,14.805 63.639,12.406 63.639,11.638 63.268,11.266 62.97,11.266 62.784,11.453 62.784,11.776 62.889,11.881 v1(62.889,11.938)
  Bottom Layer w0.19: J17.5@13.005,17.8 13.85,16.955 13.85,16.559 16.449,13.96 23.418,13.96 26.705,17.247 41.925,17.247 49.971,9.202 60.483,9.202 62.889,11.608 v1(62.889,11.938)
ETH.B_1_P: J1.5 J17.4 | length 64.3
  Top Layer w0.19: J1.5@61.61,15.605 61.61,15.152 61.58,15.122 61.58,14.946 63.979,12.547 63.979,11.497 63.38,10.898 62.858,10.898 62.444,11.312 62.444,11.776 62.339,11.881 v1(62.339,11.938)
  Bottom Layer w0.19: J17.4@15.035,17.8 14.19,16.955 14.19,16.7 16.59,14.3 23.277,14.3 26.565,17.587 42.066,17.587 50.111,9.542 60.342,9.542 62.339,11.539 v1(62.339,11.938)
ETH.C_1_N: J1.11 J17.2 | length 65
  Top Layer w0.19: v1(60.235,13.6) 60.44,13.805 60.44,15.122 60.41,15.152 J1.11@60.41,15.605
  Bottom Layer w0.19: J17.2@19.095,17.8 18.25,16.955 18.25,16.6 19.15,15.7 21.85,15.7 21.918,15.768 22.055,15.905 22.055,16.063 21.979,16.14 21.979,16.421 22.671,17.114 22.953,17.114 23.668,16.399 24.161,16.893 23.447,17.608 23.447,17.889 24.139,18.582 24.421,18.582 24.498,18.505 24.655,18.505 24.95,18.8 26.173,18.8 43.711,18.8 45.008,17.503 45.153,17.358 45.555,16.956 45.592,16.336 45.417,16.138 45.437,15.793 45.594,15.654 45.939,15.675 46.801,16.647 47.427,16.684 47.794,16.358 47.832,15.732 46.97,14.76 46.99,14.416 47.147,14.277 47.492,14.297 48.354,15.269 48.98,15.307 49.347,14.981 49.385,14.355 48.523,13.383 48.543,13.038 48.7,12.899 49.045,12.92 49.907,13.892 50.533,13.929 50.9,13.603 50.938,12.977 50.433,12.408 50.454,12.057 51.194,11.318 51.324,11.187 51.471,11.04 59.74,11.04 60.44,11.74 60.44,13.317 v1@60.235,13.522
ETH.C_1_P: J1.9 J17.3 | length 66.2
  Top Layer w0.19: J1.9@60.81,15.605 60.81,15.152 60.78,15.122 60.78,13.805 v1(60.985,13.6)
  Bottom Layer w0.19: J17.3@17.065,17.8 17.91,16.955 17.91,16.459 19.009,15.36 21.991,15.36 22.158,15.527 22.395,15.765 22.395,16.204 22.319,16.28 22.812,16.774 23.527,16.059 23.808,16.059 24.501,16.752 24.501,17.034 23.787,17.748 24.28,18.242 24.357,18.165 24.796,18.165 25.091,18.46 26.343,18.46 43.571,18.46 44.782,17.248 44.913,17.118 45.224,16.807 45.245,16.456 45.069,16.258 45.106,15.632 45.474,15.306 46.1,15.344 46.962,16.316 47.307,16.336 47.463,16.197 47.484,15.852 46.622,14.881 46.659,14.255 47.027,13.929 47.653,13.966 48.515,14.938 48.86,14.959 49.016,14.82 49.037,14.475 48.175,13.503 48.213,12.877 48.58,12.551 49.206,12.589 50.068,13.561 50.413,13.581 50.569,13.442 50.59,13.097 50.085,12.528 50.122,11.908 50.953,11.077 51.098,10.932 51.331,10.7 59.881,10.7 60.78,11.599 60.78,13.317 60.985,13.522 v1(60.985,13.6)
ETH.D_1_N: J1.15 J17.9 | length 63.5
  Top Layer w0.19: v1(58.63,13.3) 58.63,13.357 58.76,13.487 58.76,14.164 59.625,15.029 59.625,15.186 59.615,15.196 J1.15@59.615,15.6
  Bottom Layer w0.19: J17.9@18.08,20.34 18.925,21.185 18.925,21.664 19.401,22.14 22.802,22.14 24.176,22.14 24.486,21.83 24.486,19.861 25.184,19.861 25.184,22.02 25.383,22.22 26.363,22.22 26.562,22.02 26.562,19.861 27.26,19.861 27.26,22.02 27.459,22.22 28.439,22.22 28.638,22.02 28.638,19.861 29.336,19.861 29.336,22.02 29.535,22.22 30.515,22.22 30.714,22.02 30.714,20.151 30.825,20.04 31.323,20.04 45.974,20.04 53.574,12.44 58.422,12.44 58.63,12.648 v1(58.63,13.3)
ETH.D_1_P: J1.13 J17.8 | length 63.7
  Top Layer w0.19: v1(59.23,13.3) 59.23,13.357 59.1,13.487 59.1,14.023 59.965,14.888 59.965,15.107 60.005,15.147 J1.13@60.005,15.6
  Bottom Layer w0.19: J17.8@20.11,20.34 19.265,21.185 19.265,21.524 19.541,21.8 22.802,21.8 24.035,21.8 24.146,21.689 24.146,19.72 24.345,19.521 25.325,19.521 25.524,19.72 25.524,21.88 26.222,21.88 26.222,19.72 26.421,19.521 27.401,19.521 27.6,19.72 27.6,21.88 28.298,21.88 28.298,19.72 28.497,19.521 29.477,19.521 29.676,19.72 29.676,21.88 30.374,21.88 30.374,20.01 30.684,19.7 31.323,19.7 45.833,19.7 53.433,12.1 58.681,12.1 59.23,12.649 v1(59.23,13.3)
ETH.LED1_1: ETH_L1.X J1.17 J17.15 R116.1 | length 77.5
  Top Layer w0.19: v1(61.1,16.688) 59.788,16.688 59.215,16.115 59.215,15.61 J1.17@59.21,15.605 59.21,15.114 58.756,14.66 58.36,14.66 57.297,13.597 57.297,12.014 59.713,9.598 59.713,3.342 59.731,3.323 59.731,3.175 v1(59.771,3.135) 60.736,3.135 61.639,4.038 61.639,4.738 61.919,5.018 R116.1@62.364,5.018
  Bottom Layer w0.19: v1(61.1,16.688) 61.157,16.688 61.314,16.845 61.845,16.845 ETH_L1.X@62,17
  Bottom Layer w0.3: J17.15@8.54,7.39 8.691,7.39 12.481,3.6 25.3,3.6 26.2,2.7 41.908,2.7 42.848,3.64 45.46,3.64 47.6,1.5 58.8,1.5 59.771,2.471 v1(59.771,3.135)
ETH.LED2_1: ETH_L2.X J1.19 R96.2 R117.1 | length 37.5
  Top Layer w0.2: v1(59.137,16.678) 58.86,16.402 58.86,16.032 58.81,15.981 J1.19@58.81,15.605 58.81,15.201 58.614,15.005 58.206,15.005 56.952,13.75 56.952,11.579 59.318,9.213 59.318,2.871 59.123,2.676 v1(59.123,2.654) 61.353,2.654 62.364,3.665 R117.1@62.364,4.138
  Top Layer w0.3: R96.2@44.383,4.6 45.188,4.6 v1(45.51,4.279)
  Bottom Layer w0.2: v1(59.137,16.678) 59.142,16.678 59.351,16.887 59.887,16.887 ETH_L2.X@60,17
  Bottom Layer w0.3: v1(45.51,4.279) 45.51,4.29 47.792,2.008 58.45,2.008 59.096,2.654 v1(59.123,2.654)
